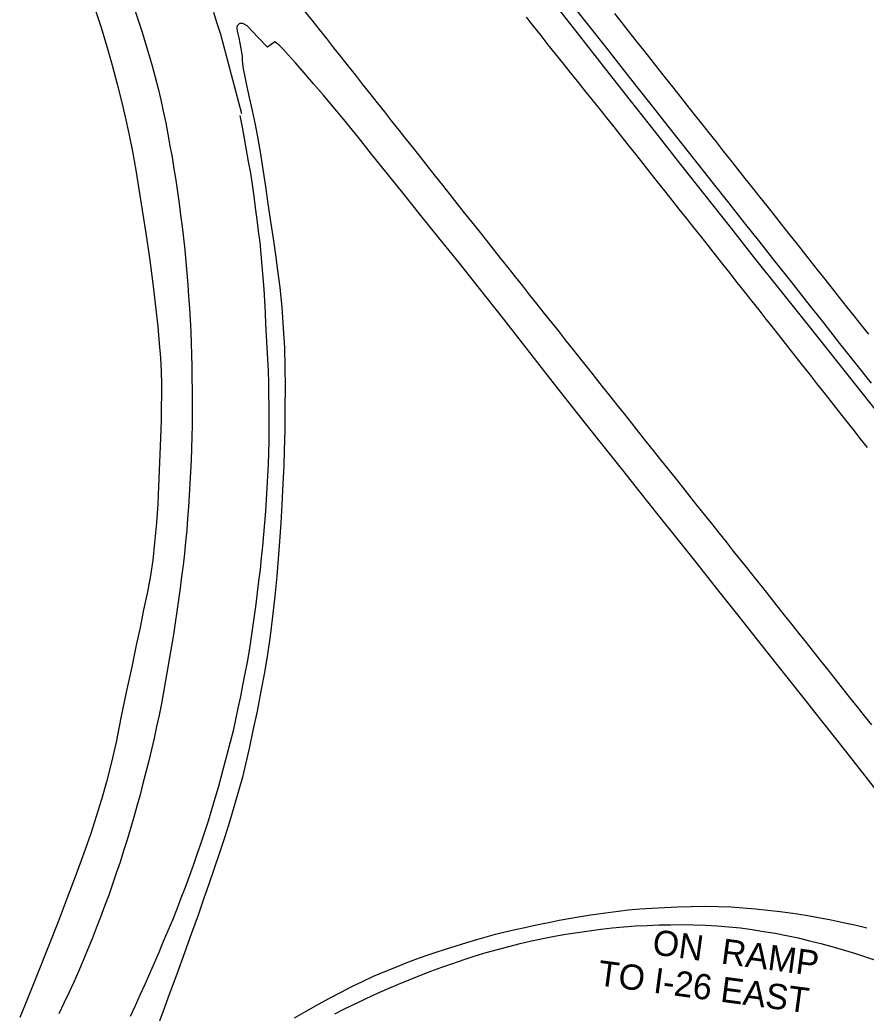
# Model space of a CAD drawing. Extents: x 1948091 to 1975253, y 787267 to 823306.
# Drawn here: x 1963742.9 to 1963923.8, y 804833.6 to 805045.9 of the extents above; entities that cross this region are included whole.
import ezdxf

# ---------------------------------------------------------------- set-up
doc = ezdxf.new("R2010")
doc.units = 0
for name, color, linetype in [('RD_EX_Pavement_Markings', 7, 'Continuous'), ('RD_EX_Road', 7, 'Continuous'), ('RD_TX_RoadID', 7, 'Continuous')]:
    doc.layers.add(name, color=color, linetype=linetype)

msp = doc.modelspace()

# ---------------------------------------------------------------- linework, layer by layer
at = {"layer": 'RD_EX_Pavement_Markings'}
for points in [[(1963767.45, 805047.94), (1963768.23, 805045.57), (1963769.02, 805043.2), (1963769.75, 805040.81), (1963770.47, 805038.42), (1963771.19, 805036.03), (1963771.82, 805033.61), (1963772.45, 805031.2), (1963773.02, 805028.76), (1963773.54, 805026.32), (1963774.06, 805023.88), (1963774.52, 805021.42), (1963774.97, 805018.96), (1963775.42, 805016.51), (1963775.8, 805014.04), (1963776.19, 805011.57), (1963776.57, 805009.1), (1963776.92, 805006.63), (1963777.24, 805004.15), (1963777.57, 805001.67), (1963777.84, 804999.19), (1963778.11, 804996.71), (1963778.38, 804994.22), (1963778.58, 804991.73), (1963778.77, 804989.24), (1963778.95, 804986.75), (1963779.14, 804984.26), (1963779.26, 804981.76), (1963779.39, 804979.27), (1963779.52, 804976.77), (1963779.59, 804974.27), (1963779.63, 804971.77), (1963779.67, 804969.27), (1963779.69, 804966.78), (1963779.7, 804964.28), (1963779.71, 804961.78), (1963779.7, 804959.28), (1963779.63, 804956.78), (1963779.55, 804954.28), (1963779.48, 804951.78), (1963779.35, 804949.29), (1963779.22, 804946.79), (1963779.09, 804944.3), (1963778.91, 804941.8), (1963778.72, 804939.31), (1963778.54, 804936.82), (1963778.3, 804934.33), (1963778.04, 804931.84), (1963777.79, 804929.36), (1963777.46, 804926.88), (1963777.13, 804924.4), (1963776.79, 804921.92), (1963776.43, 804919.45), (1963776.07, 804916.98), (1963775.71, 804914.5), (1963775.3, 804912.04), (1963774.87, 804909.57), (1963774.45, 804907.11), (1963774.02, 804904.65), (1963773.57, 804902.19), (1963773.12, 804899.73), (1963772.64, 804897.28), (1963772.11, 804894.83), (1963771.57, 804892.39), (1963771.02, 804889.95), (1963770.43, 804887.52), (1963769.84, 804885.09), (1963769.2, 804882.68), (1963768.56, 804880.26), (1963767.91, 804877.85), (1963767.22, 804875.44), (1963766.53, 804873.04), (1963765.81, 804870.65), (1963765.06, 804868.26), (1963764.31, 804865.88), (1963763.5, 804863.51), (1963762.68, 804861.15), (1963761.87, 804858.79), (1963760.98, 804856.45), (1963760.1, 804854.11), (1963759.21, 804851.77), (1963758.31, 804849.44), (1963757.35, 804847.13), (1963756.4, 804844.82), (1963755.42, 804842.52), (1963754.39, 804840.24), (1963753.37, 804837.96), (1963752.31, 804835.7), (1963751.24, 804833.44)], [(1963790.31, 805025.8), (1963789.67, 805028.22), (1963789.04, 805030.64), (1963788.41, 805033.05), (1963787.77, 805035.47), (1963787.14, 805037.89), (1963786.51, 805040.3), (1963785.81, 805042.7), (1963785.06, 805045.08), (1963784.31, 805047.46)], [(1963803.75, 805047.73), (1963805.3, 805045.77), (1963806.85, 805043.81), (1963808.4, 805041.85), (1963809.94, 805039.89), (1963811.49, 805037.93), (1963813.04, 805035.97), (1963814.59, 805034.01), (1963816.14, 805032.05), (1963817.68, 805030.09), (1963819.24, 805028.13), (1963820.79, 805026.17), (1963822.34, 805024.22), (1963823.89, 805022.26), (1963825.45, 805020.31), (1963827, 805018.35), (1963828.55, 805016.39), (1963830.1, 805014.44), (1963831.66, 805012.48), (1963833.21, 805010.52), (1963834.76, 805008.57), (1963836.31, 805006.61), (1963837.86, 805004.65), (1963839.42, 805002.7), (1963840.97, 805000.74), (1963842.52, 804998.79), (1963844.07, 804996.83), (1963845.63, 804994.88), (1963847.18, 804992.92), (1963848.73, 804990.96), (1963850.28, 804989.01), (1963851.84, 804987.05), (1963853.39, 804985.1), (1963854.94, 804983.14), (1963856.5, 804981.19), (1963858.05, 804979.23), (1963859.6, 804977.28), (1963861.16, 804975.32), (1963862.71, 804973.37), (1963864.27, 804971.41), (1963865.82, 804969.46), (1963867.37, 804967.5), (1963868.93, 804965.55), (1963870.48, 804963.59), (1963872.03, 804961.64), (1963873.59, 804959.68), (1963875.14, 804957.73), (1963876.7, 804955.78), (1963878.26, 804953.82), (1963879.81, 804951.87), (1963881.37, 804949.92), (1963882.92, 804947.97), (1963884.48, 804946.01), (1963886.04, 804944.06), (1963887.59, 804942.11), (1963889.15, 804940.15), (1963890.71, 804938.2), (1963892.26, 804936.25), (1963893.82, 804934.3), (1963895.37, 804932.34), (1963896.93, 804930.39), (1963898.49, 804928.44), (1963900.04, 804926.48), (1963901.59, 804924.53), (1963903.15, 804922.57), (1963904.7, 804920.62), (1963906.25, 804918.66), (1963907.81, 804916.71), (1963909.36, 804914.75), (1963910.91, 804912.8), (1963912.47, 804910.84), (1963914.02, 804908.89), (1963915.58, 804906.94), (1963917.13, 804904.98), (1963918.67, 804903.02), (1963920.22, 804901.06), (1963921.77, 804899.1), (1963923.32, 804897.15), (1963924.87, 804895.19)], [(1963851.1, 805046.41), (1963852.65, 805044.46), (1963854.2, 805042.5), (1963855.75, 805040.54), (1963857.31, 805038.59), (1963858.87, 805036.64), (1963860.43, 805034.69), (1963861.99, 805032.74), (1963863.55, 805030.79), (1963865.11, 805028.84), (1963866.67, 805026.9), (1963868.23, 805024.95), (1963869.8, 805023), (1963871.35, 805021.05), (1963872.91, 805019.1), (1963874.46, 805017.14), (1963876.01, 805015.19), (1963877.56, 805013.23), (1963879.11, 805011.27), (1963880.66, 805009.32), (1963882.21, 805007.36), (1963883.76, 805005.4), (1963885.31, 805003.45), (1963886.86, 805001.49), (1963888.41, 804999.53), (1963889.96, 804997.58), (1963891.51, 804995.62), (1963893.06, 804993.66), (1963894.6, 804991.7), (1963896.15, 804989.74), (1963897.7, 804987.78), (1963899.24, 804985.82), (1963900.79, 804983.86), (1963902.34, 804981.9), (1963903.88, 804979.94), (1963905.43, 804977.98), (1963906.98, 804976.02), (1963908.52, 804974.06), (1963910.07, 804972.1), (1963911.62, 804970.14), (1963913.16, 804968.18), (1963914.71, 804966.22), (1963916.25, 804964.26), (1963917.8, 804962.3), (1963919.34, 804960.34), (1963920.89, 804958.37), (1963922.43, 804956.41), (1963923.97, 804954.45)], [(1963869.98, 805047.2), (1963871.52, 805045.24), (1963873.07, 805043.28), (1963874.62, 805041.32), (1963876.17, 805039.37), (1963877.72, 805037.41), (1963879.27, 805035.45), (1963880.82, 805033.49), (1963882.37, 805031.53), (1963883.92, 805029.58), (1963885.47, 805027.62), (1963887.02, 805025.66), (1963888.57, 805023.7), (1963890.12, 805021.74), (1963891.67, 805019.79), (1963893.21, 805017.83), (1963894.76, 805015.87), (1963896.31, 805013.91), (1963897.86, 805011.96), (1963899.42, 805010), (1963900.97, 805008.04), (1963902.52, 805006.08), (1963904.07, 805004.13), (1963905.62, 805002.17), (1963907.17, 805000.21), (1963908.72, 804998.26), (1963910.27, 804996.3), (1963911.82, 804994.34), (1963913.37, 804992.39), (1963914.92, 804990.43), (1963916.47, 804988.47), (1963918.02, 804986.52), (1963919.58, 804984.56), (1963921.13, 804982.6), (1963922.68, 804980.64), (1963924.23, 804978.69)], [(1963789.93, 805025.41), (1963790.37, 805022.95), (1963790.82, 805020.49), (1963791.27, 805018.03), (1963791.71, 805015.57), (1963792.16, 805013.12), (1963792.55, 805010.65), (1963792.87, 805008.17), (1963793.2, 805005.69), (1963793.52, 805003.21), (1963793.85, 805000.73), (1963794.17, 804998.26), (1963794.39, 804995.77), (1963794.61, 804993.28), (1963794.83, 804990.79), (1963795.02, 804988.29), (1963795.15, 804985.8), (1963795.28, 804983.3), (1963795.4, 804980.81), (1963795.53, 804978.31), (1963795.66, 804975.81), (1963795.79, 804973.32), (1963795.92, 804970.82), (1963796, 804968.32), (1963796.04, 804965.83), (1963796.08, 804963.33), (1963796.12, 804960.83), (1963796.11, 804958.33), (1963796.07, 804955.83), (1963796.02, 804953.33), (1963795.97, 804950.83), (1963795.83, 804948.34), (1963795.69, 804945.84), (1963795.54, 804943.34), (1963795.4, 804940.85), (1963795.18, 804938.36), (1963794.95, 804935.87), (1963794.72, 804933.38), (1963794.48, 804930.89), (1963794.23, 804928.41), (1963793.92, 804925.93), (1963793.61, 804923.45), (1963793.3, 804920.97), (1963792.96, 804918.49), (1963792.61, 804916.01), (1963792.25, 804913.54), (1963791.9, 804911.07), (1963791.45, 804908.61), (1963790.97, 804906.15), (1963790.49, 804903.7), (1963790.01, 804901.25), (1963789.49, 804898.8), (1963788.97, 804896.36), (1963788.44, 804893.91), (1963787.85, 804891.48), (1963787.22, 804889.07), (1963786.58, 804886.65), (1963785.94, 804884.23), (1963785.26, 804881.83), (1963784.54, 804879.43), (1963783.83, 804877.04), (1963783.12, 804874.64), (1963782.34, 804872.26), (1963781.54, 804869.9), (1963780.73, 804867.53), (1963779.93, 804865.16), (1963779.09, 804862.81), (1963778.19, 804860.47), (1963777.3, 804858.14), (1963776.4, 804855.81), (1963775.48, 804853.48), (1963774.51, 804851.18), (1963773.53, 804848.88), (1963772.56, 804846.58), (1963771.58, 804844.27), (1963770.6, 804841.97), (1963769.58, 804839.69), (1963768.55, 804837.42), (1963767.51, 804835.14), (1963766.47, 804832.87)], [(1963810.2, 804833.42), (1963812.42, 804834.57), (1963814.68, 804835.65), (1963816.93, 804836.72), (1963819.2, 804837.77), (1963821.48, 804838.78), (1963823.78, 804839.77), (1963826.09, 804840.72), (1963828.4, 804841.66), (1963830.74, 804842.53), (1963833.09, 804843.4), (1963835.44, 804844.22), (1963837.81, 804845.04), (1963840.18, 804845.81), (1963842.58, 804846.52), (1963844.98, 804847.2), (1963847.39, 804847.84), (1963849.81, 804848.47), (1963852.25, 804849.01), (1963854.69, 804849.53), (1963857.14, 804850.03), (1963859.6, 804850.44), (1963862.07, 804850.84), (1963864.54, 804851.19), (1963867.02, 804851.53), (1963869.5, 804851.8), (1963871.99, 804852.02), (1963874.47, 804852.22), (1963876.97, 804852.33), (1963879.47, 804852.43), (1963881.96, 804852.49), (1963884.46, 804852.52), (1963886.95, 804852.47), (1963889.45, 804852.38), (1963891.94, 804852.25), (1963894.43, 804852.06), (1963896.91, 804851.8), (1963899.38, 804851.44), (1963901.85, 804851.07), (1963904.32, 804850.68), (1963906.76, 804850.19), (1963909.21, 804849.68), (1963911.63, 804849.08), (1963914.05, 804848.47), (1963916.45, 804847.81), (1963918.86, 804847.15), (1963921.24, 804846.4), (1963923.61, 804845.62), (1963925.97, 804844.81)]]:
    msp.add_lwpolyline(points, dxfattribs=at)
at = {"layer": 'RD_EX_Road'}
for points in [[(1963857.2, 805049.15), (1963862.72, 805042.13), (1963868.06, 805035.34), (1963873.35, 805028.62), (1963878.74, 805021.76), (1963884.1, 805014.97), (1963889.27, 805008.41), (1963894.45, 805001.85), (1963899.84, 804995.02), (1963905.3, 804988.14), (1963910.71, 804981.37), (1963916.02, 804974.74), (1963921.19, 804968.23), (1963926.39, 804961.68), (1963931.75, 804954.88), (1963936.75, 804948.53), (1963940.85, 804943.33), (1963944.69, 804938.45), (1963948.93, 804933.06), (1963953.68, 804927.05), (1963957.01, 804922.86), (1963959.07, 804920.26), (1963959.34, 804919.9)], [(1963861.39, 805048.53), (1963864.72, 805044.31), (1963868.03, 805040.08), (1963871.34, 805035.86), (1963874.67, 805031.63), (1963878, 805027.4), (1963881.34, 805023.17), (1963884.64, 805019), (1963887.85, 805014.94), (1963891.06, 805010.87), (1963894.38, 805006.68), (1963897.71, 805002.48), (1963900.95, 804998.4), (1963904.25, 804994.25), (1963907.72, 804989.85), (1963911.24, 804985.39), (1963914.69, 804981.03), (1963918.1, 804976.73), (1963921.49, 804972.44), (1963924.84, 804968.2)], [(1963758.92, 805048.27), (1963760.23, 805044.24), (1963761.45, 805040.19), (1963762.61, 805036.14), (1963763.69, 805032.13), (1963764.62, 805028.47), (1963765.4, 805025.11), (1963766.17, 805021.55), (1963766.94, 805017.72), (1963767.65, 805013.76), (1963768.31, 805009.66), (1963769.04, 805005.18), (1963769.84, 805000.28), (1963770.6, 804995.03), (1963771.3, 804989.55), (1963771.89, 804984.6), (1963772.35, 804980.32), (1963772.69, 804976.69), (1963772.92, 804973.64), (1963773.06, 804970.73), (1963773.12, 804967.92), (1963773.14, 804965.5), (1963773.11, 804963.33), (1963773.05, 804960.34), (1963772.95, 804956.53), (1963772.82, 804952.94), (1963772.68, 804949.65), (1963772.52, 804946.17), (1963772.34, 804942.4), (1963772.06, 804938.34), (1963771.69, 804934.09), (1963771.27, 804930.36), (1963770.78, 804927.14), (1963770.14, 804923.63), (1963769.34, 804919.77), (1963768.56, 804915.99), (1963767.77, 804912.22), (1963766.78, 804907.61), (1963765.6, 804902.16), (1963764.47, 804896.73), (1963763.44, 804891.52), (1963762.43, 804886.95), (1963761.42, 804883.02), (1963760.35, 804879.26), (1963759.21, 804875.59), (1963757.96, 804871.8), (1963756.57, 804867.8), (1963754.92, 804863.27), (1963753.02, 804858.2), (1963751.04, 804853.07), (1963749, 804847.88), (1963746.78, 804842.32), (1963744.51, 804836.63), (1963742.88, 804832.69)], [(1963926.65, 804880.41), (1963921, 804887.55), (1963917.27, 804892.27), (1963913.94, 804896.47), (1963910.51, 804900.8), (1963907.18, 804905.02), (1963901.39, 804912.33), (1963896.64, 804918.34), (1963892.09, 804924.07), (1963887.62, 804929.65), (1963883.35, 804935), (1963879.3, 804940.11), (1963875.44, 804944.96), (1963871.73, 804949.65), (1963867.77, 804954.63), (1963863.31, 804960.25), (1963857.17, 804968.04), (1963853.4, 804972.85), (1963849.62, 804977.66), (1963846.32, 804981.87), (1963841.13, 804988.46), (1963836.84, 804993.85), (1963832.45, 804999.27), (1963828.3, 805004.38), (1963824.7, 805008.86), (1963821.38, 805013.02), (1963818.06, 805017.18), (1963815.23, 805020.72), (1963813.36, 805023.06), (1963811.79, 805024.98), (1963809.86, 805027.27), (1963807.76, 805029.74), (1963805.65, 805032.19), (1963803.63, 805034.53), (1963801.78, 805036.64), (1963800.23, 805038.38), (1963799.11, 805039.63), (1963798.21, 805040.5), (1963797.77, 805040.84), (1963797.35, 805041.13), (1963795.84, 805040.02), (1963793.81, 805042.06), (1963791.46, 805044.57), (1963790.91, 805044.9), (1963790.67, 805045), (1963790.45, 805045.07), (1963790.26, 805045.1), (1963790.08, 805045.09), (1963789.91, 805045.05), (1963789.76, 805044.98), (1963789.63, 805044.89), (1963789.52, 805044.78), (1963789.43, 805044.67), (1963789.36, 805044.55), (1963789.31, 805044.41), (1963789.28, 805044.27), (1963789.27, 805044.11), (1963789.28, 805043.95), (1963789.36, 805043.51), (1963789.5, 805042.88), (1963789.69, 805042.01), (1963789.92, 805040.87), (1963790.13, 805039.73), (1963790.28, 805038.88), (1963790.37, 805038.14), (1963790.42, 805037.33), (1963790.49, 805036.43), (1963790.61, 805035.42), (1963790.86, 805034.01), (1963791.32, 805031.89), (1963791.9, 805029.3), (1963792.52, 805026.49), (1963793.15, 805023.52), (1963793.74, 805020.46), (1963794.3, 805017.26), (1963794.83, 805013.86), (1963795.36, 805010.28), (1963795.9, 805006.54), (1963796.44, 805002.77), (1963796.99, 804999.13), (1963797.51, 804995.62), (1963797.98, 804992.28), (1963798.42, 804988.68), (1963798.84, 804984.44), (1963799.19, 804980), (1963799.41, 804975.78), (1963799.53, 804971.63), (1963799.57, 804967.37), (1963799.55, 804962.91), (1963799.49, 804958.18), (1963799.4, 804953.86), (1963799.29, 804950.64), (1963799.15, 804947.97), (1963799, 804945.28), (1963798.84, 804942.21), (1963798.63, 804938.38), (1963798.39, 804934.36), (1963798.12, 804930.7), (1963797.78, 804926.97), (1963797.37, 804922.73), (1963796.89, 804918.35), (1963796.38, 804914.24), (1963795.8, 804910.28), (1963795.14, 804906.39), (1963794.4, 804902.4), (1963793.57, 804898.16), (1963792.71, 804893.96), (1963791.88, 804890.13), (1963791.11, 804886.77), (1963790.44, 804884.01), (1963789.71, 804881.31), (1963788.78, 804878.12), (1963787.73, 804874.69), (1963786.66, 804871.27), (1963785.55, 804867.87), (1963784.41, 804864.48), (1963783.28, 804861.15), (1963782.15, 804857.92), (1963780.96, 804854.53), (1963779.6, 804850.71), (1963778.08, 804846.51), (1963776.43, 804841.95), (1963774.82, 804837.55), (1963773.43, 804833.8), (1963772.2, 804830.57)], [(1963801.57, 804832.56), (1963804.05, 804834), (1963806.73, 804835.51), (1963809.2, 804836.86), (1963811.55, 804838.1), (1963813.82, 804839.26), (1963816.1, 804840.38), (1963818.48, 804841.46), (1963820.88, 804842.49), (1963823.22, 804843.45), (1963825.44, 804844.33), (1963827.49, 804845.1), (1963829.51, 804845.81), (1963831.63, 804846.53), (1963833.85, 804847.25), (1963836.16, 804847.99), (1963838.42, 804848.7), (1963840.52, 804849.31), (1963842.53, 804849.88), (1963844.55, 804850.44), (1963846.63, 804850.98), (1963848.78, 804851.47), (1963850.84, 804851.91), (1963852.64, 804852.3), (1963854.37, 804852.67), (1963856.21, 804853.06), (1963858.15, 804853.45), (1963860.2, 804853.83), (1963862.29, 804854.18), (1963864.39, 804854.52), (1963866.49, 804854.83), (1963868.6, 804855.12), (1963870.75, 804855.4), (1963873, 804855.64), (1963875.38, 804855.86), (1963877.94, 804856.04), (1963880.66, 804856.19), (1963883.48, 804856.3), (1963886.37, 804856.37), (1963889.27, 804856.42), (1963892.12, 804856.41), (1963894.84, 804856.31), (1963897.48, 804856.13), (1963900.1, 804855.88), (1963902.73, 804855.59), (1963905.38, 804855.28), (1963908.08, 804854.93), (1963910.85, 804854.5), (1963913.6, 804854.02), (1963916.26, 804853.5), (1963918.84, 804852.97), (1963921.35, 804852.44), (1963923.89, 804851.85)]]:
    msp.add_lwpolyline(points, dxfattribs=at)

# ---------------------------------------------------------------- texts
at = {"layer": 'RD_TX_RoadID'}
for s, p in [('ON  RAMP', (1963877.87, 804846.18)), ('TO I-26 EAST', (1963866.18, 804839.57))]:
    msp.add_text(s, height=5.4, rotation=352.3959, dxfattribs=at).set_placement(p)

doc.saveas('drawing.dxf')
